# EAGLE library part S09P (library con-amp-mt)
AMP MT CONNECTOR
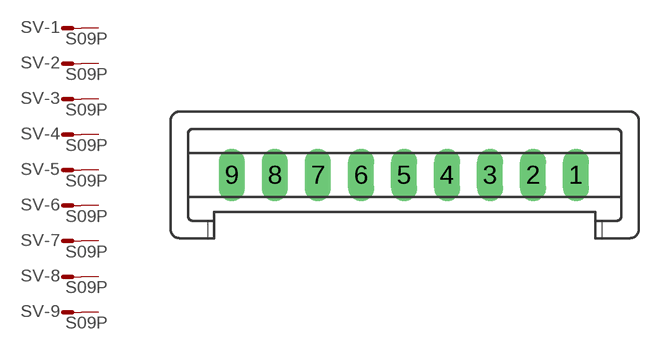
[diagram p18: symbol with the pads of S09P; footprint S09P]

Designator prefix SV; gates -1=M -2=M -3=M -4=M -5=M -6=M -7=M -8=M -9=M

## S09P (OC_FARNELL: unknown; OC_NEWARK: unknown)  [S09P]
1  -1:S  pas
2  -2:S  pas
3  -3:S  pas
4  -4:S  pas
5  -5:S  pas
6  -6:S  pas
7  -7:S  pas
8  -8:S  pas
9  -9:S  pas

## Footprint S09P (pad centres in mm)
AMP MT CONNECTOR
drill 1.016 long: 1 10,0; 2 7.5,0; 3 5,0; 4 2.5,0; 5 0,0; 6 -2.5,0; 7 -5,0; 8 -7.5,0; 9 -10,0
